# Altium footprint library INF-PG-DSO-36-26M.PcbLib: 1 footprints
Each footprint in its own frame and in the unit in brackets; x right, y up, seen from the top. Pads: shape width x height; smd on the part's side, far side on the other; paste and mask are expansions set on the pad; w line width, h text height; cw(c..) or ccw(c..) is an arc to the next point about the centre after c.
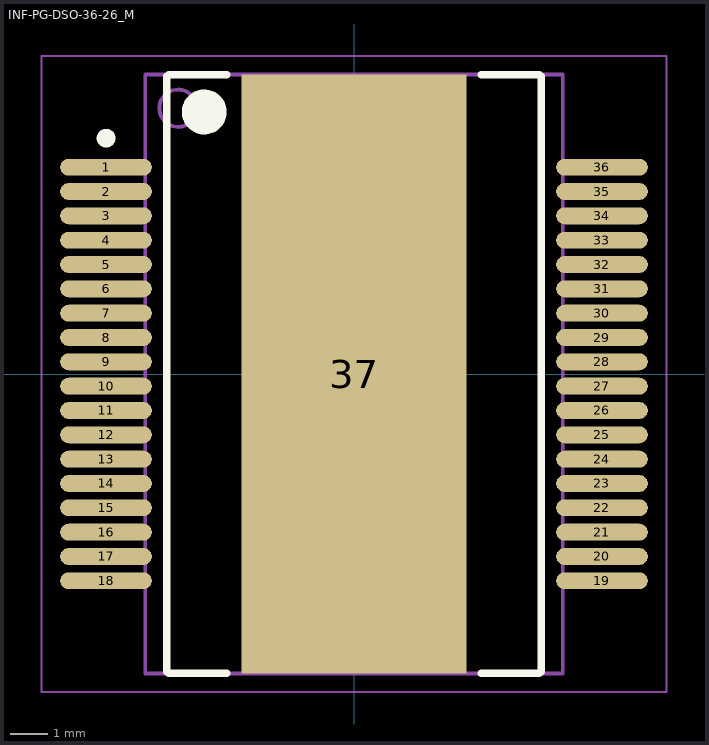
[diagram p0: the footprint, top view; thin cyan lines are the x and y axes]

## INF-PG-DSO-36-26_M [mm] "SOP, 36-Leads, Body 15.9x11mm, Pitch 0.65mm, Thermal Pad 16x6mm, IPC Low Density"
height 3.5
pads (37):
  oval 2.45x0.45 smd: 1(-6.625,5.525) 2(-6.625,4.875) 3(-6.625,4.225) 4(-6.625,3.575) 5(-6.625,2.925) 6(-6.625,2.275) 7(-6.625,1.625) 8(-6.625,0.975) 9(-6.625,0.325) 10(-6.625,-0.325) 11(-6.625,-0.975) 12(-6.625,-1.625) 13(-6.625,-2.275) 14(-6.625,-2.925) 15(-6.625,-3.575) 16(-6.625,-4.225) 17(-6.625,-4.875) 18(-6.625,-5.525) 19(6.625,-5.525) 20(6.625,-4.875) 21(6.625,-4.225) 22(6.625,-3.575) 23(6.625,-2.925) 24(6.625,-2.275) 25(6.625,-1.625) 26(6.625,-0.975) 27(6.625,-0.325) 28(6.625,0.325) 29(6.625,0.975) 30(6.625,1.625) 31(6.625,2.275) 32(6.625,2.925) 33(6.625,3.575) 34(6.625,4.225) 35(6.625,4.875) 36(6.625,5.525)
  rect 6x16 smd: 37(0,0)
Top Overlay:
  circle w0.25: c-6.625,6.3 r0.125
  circle w0.6: c-4,7 r0.3
  lines w0.2: -3.4,-8 -4.954,-8 -5,-7.954 -5,7.954 -4.954,8 -3.4,8 ; 3.4,-8 4.954,-8 5,-7.954 5,7.954 4.954,8 3.4,8
Mechanical 13:
  circle w0.1: c-4.7,7.1 r0.5
  lines w0.1: -5.575,-8 -5.575,8 5.575,8 5.575,-8 -5.575,-8
Mechanical 15:
  lines w0.05: -8.35,-8.5 -8.35,8.5 8.35,8.5 8.35,-8.5 -8.35,-8.5
  lines w0.1: -0.5,0 0.5,0 ; 0,-0.5 0,0.5
3D body: height 3.5, standoff 0, extent -5.575,-8 5.575,8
